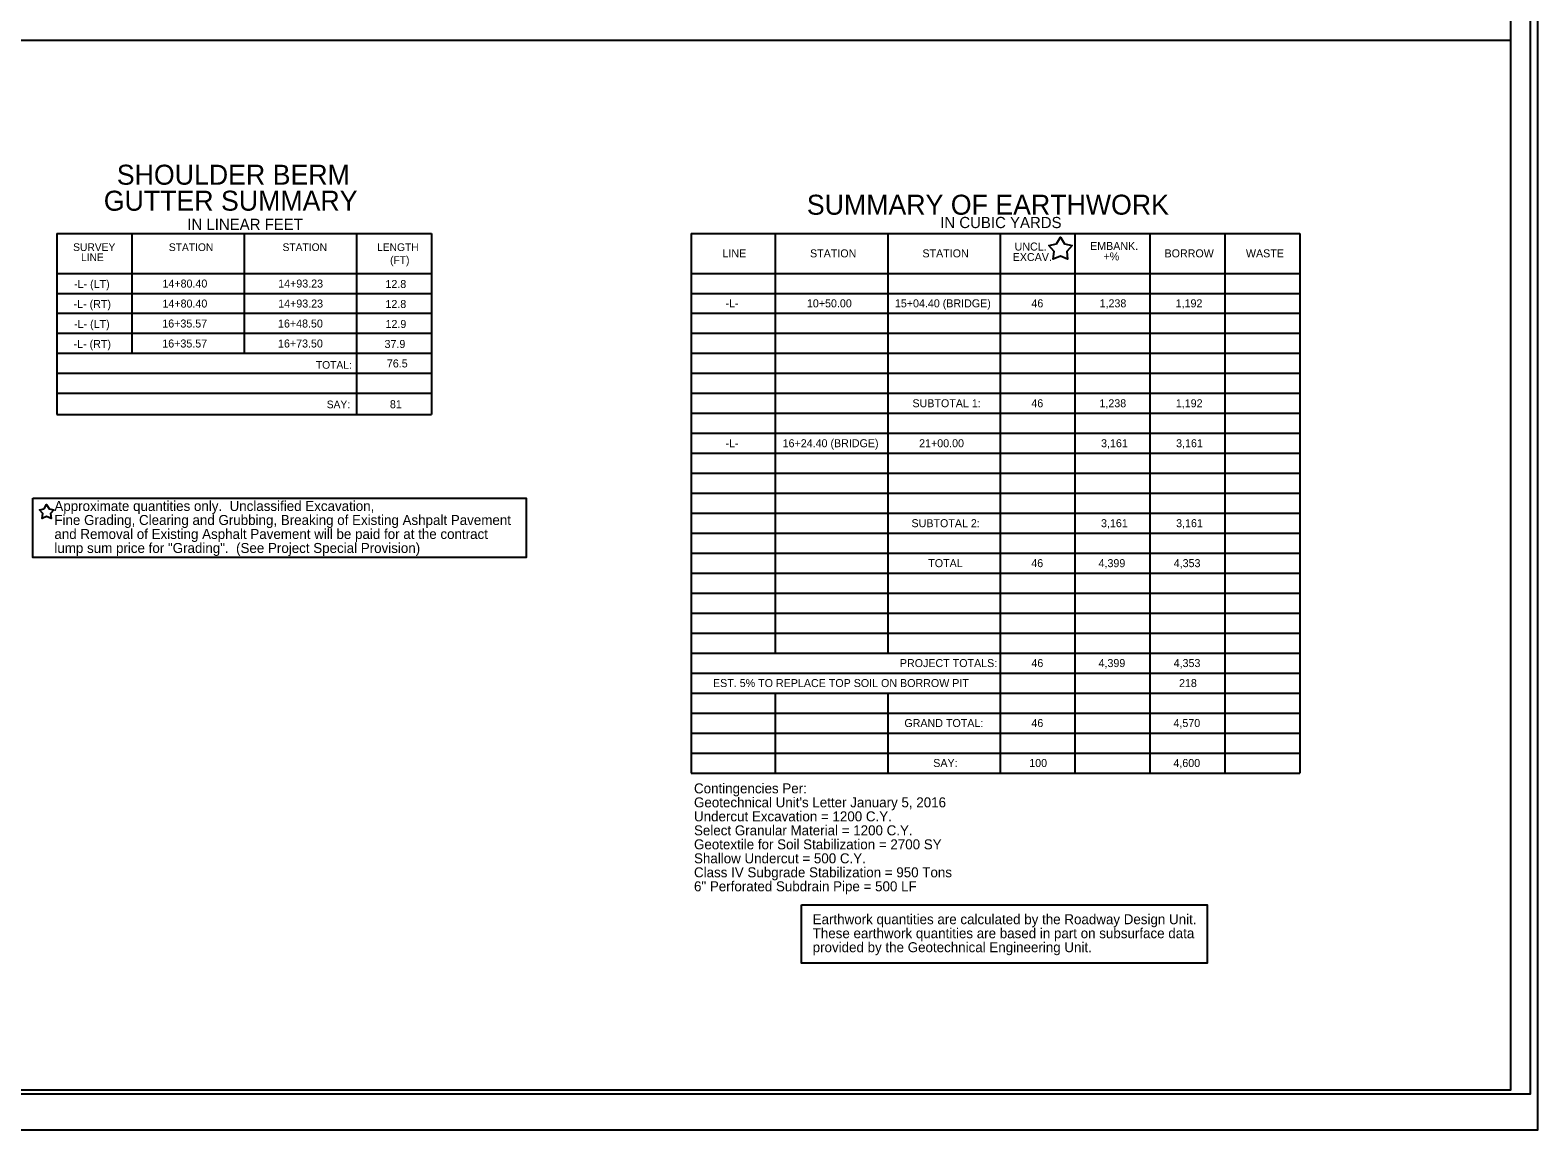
# Model space of a CAD drawing. Extents: x 9833 to 11517, y 9975 to 11331.
# Drawn here: x 10574 to 11517, y 9975 to 10663 of the extents above; entities that cross this region are included whole.
import ezdxf

# ---------------------------------------------------------------- set-up
doc = ezdxf.new("R2010")
doc.units = 0
for name, color, linetype in [('Prop Dimension Text', 7, 'Continuous'), ('Sheet Cutting Line CELL', 7, 'Continuous'), ('Sheet Pipe Summary CELL', 7, 'Continuous'), ('Sheet Plot Border Inside CELL', 7, 'Continuous'), ('Sheet Plot Border Outside CELL', 7, 'Continuous'), ('Sheet Summary CELL', 7, 'Continuous'), ('Sheet Summary Combination CELL', 7, 'Continuous'), ('Sheet Summary Combination Grid CELL', 7, 'Continuous'), ('Sheet Summary Earthwork CELL', 7, 'Continuous')]:
    doc.layers.add(name, color=color, linetype=linetype)

msp = doc.modelspace()

# ---------------------------------------------------------------- linework, layer by layer
at = {"layer": 'Sheet Cutting Line CELL'}
msp.add_line((9833, 9975), (11517, 9975), dxfattribs=at)
at = {"layer": 'Sheet Plot Border Inside CELL'}
msp.add_lwpolyline([(11512.5, 11052.55), (9846, 11052.55), (9846, 9997.45), (11512.5, 9997.45)], close=True, dxfattribs=at)
at = {"layer": 'Sheet Plot Border Outside CELL'}
msp.add_lwpolyline([(11517, 11075), (9833, 11075), (9833, 9975), (11517, 9975)], close=True, dxfattribs=at)
at = {"layer": 'Sheet Summary CELL'}
msp.add_lwpolyline([(11500, 11050), (10000, 11050), (10000, 10000), (11500, 10000)], close=True, dxfattribs=at)
at = {"layer": 'Sheet Summary Combination CELL'}
for p, q in [((10731.53, 10535.63), (10731.53, 10535.63)), ((10737.78, 10535.53), (10737.78, 10535.53)), ((10746.83, 10535.73), (10746.83, 10535.73)), ((10752.43, 10535.63), (10752.43, 10535.63)), ((11134.16, 10535.63), (11134.16, 10535.63)), ((11140.41, 10535.53), (11140.41, 10535.53)), ((11149.46, 10535.73), (11149.46, 10535.73)), ((11155.06, 10535.63), (11155.06, 10535.63))]:
    msp.add_line(p, q, dxfattribs=at)
at = {"layer": 'Sheet Summary Combination Grid CELL'}
for p, q in [((10000, 10656.54), (11500, 10656.54)), ((10590.28, 10535.68), (10824.73, 10535.68)), ((10590.28, 10535.68), (10590.28, 10422.38)), ((10637.18, 10535.68), (10637.18, 10460.68)), ((10707.53, 10535.68), (10707.53, 10460.68)), ((10777.83, 10535.68), (10777.83, 10422.38)), ((10824.73, 10535.68), (10824.73, 10422.38)), ((10987.07, 10535.68), (11368.06, 10535.68)), ((10987.07, 10535.68), (10987.07, 10198.18)), ((11039.81, 10535.68), (11039.81, 10273.18)), ((11110.16, 10535.68), (11110.16, 10273.18)), ((11180.46, 10535.68), (11180.46, 10198.18)), ((11227.36, 10535.68), (11227.36, 10198.18)), ((11274.26, 10535.68), (11274.26, 10198.18)), ((11321.16, 10535.68), (11321.16, 10198.18)), ((11368.06, 10535.68), (11368.06, 10198.18)), ((10590.28, 10510.68), (10824.73, 10510.68)), ((10987.07, 10510.68), (11368.06, 10510.68)), ((10590.28, 10498.18), (10824.73, 10498.18)), ((10987.07, 10498.18), (11368.06, 10498.18)), ((10590.28, 10485.68), (10824.73, 10485.68)), ((10987.07, 10485.68), (11368.06, 10485.68)), ((10590.28, 10473.18), (10824.73, 10473.18)), ((10987.07, 10473.18), (11368.06, 10473.18)), ((10590.28, 10460.68), (10824.73, 10460.68)), ((10987.07, 10460.68), (11368.06, 10460.68)), ((10590.28, 10448.18), (10824.73, 10448.18)), ((10987.07, 10448.18), (11368.06, 10448.18)), ((10590.28, 10435.68), (10824.73, 10435.68)), ((10987.07, 10435.68), (11368.06, 10435.68)), ((10590.28, 10422.38), (10824.73, 10422.38)), ((10987.07, 10423.18), (11368.06, 10423.18)), ((10987.07, 10410.68), (11368.06, 10410.68)), ((10987.07, 10398.18), (11368.06, 10398.18)), ((10987.07, 10385.68), (11368.06, 10385.68)), ((10987.07, 10373.18), (11368.06, 10373.18)), ((10987.07, 10360.68), (11368.06, 10360.68)), ((10987.07, 10348.18), (11368.06, 10348.18)), ((10987.07, 10335.68), (11368.06, 10335.68)), ((10987.07, 10323.18), (11368.06, 10323.18)), ((10987.07, 10310.68), (11368.06, 10310.68)), ((10987.07, 10298.18), (11368.06, 10298.18)), ((10987.07, 10285.68), (11368.06, 10285.68)), ((10987.07, 10273.18), (11368.06, 10273.18)), ((10987.07, 10260.68), (11368.06, 10260.68)), ((10987.07, 10248.18), (11368.06, 10248.18)), ((11039.81, 10248.18), (11039.81, 10198.18)), ((11110.16, 10248.18), (11110.16, 10198.18)), ((10987.07, 10235.68), (11368.06, 10235.68)), ((10987.07, 10223.18), (11368.06, 10223.18)), ((10987.07, 10210.68), (11368.06, 10210.68)), ((10987.07, 10198.18), (11368.06, 10198.18))]:
    msp.add_line(p, q, dxfattribs=at)
at = {"layer": 'Sheet Summary Earthwork CELL'}
for points in [[(11215.83, 10529.07), (11218.28, 10533.32), (11220.73, 10529.07), (11225.53, 10528.05), (11222.25, 10524.41), (11222.76, 10519.53), (11218.28, 10521.52), (11213.8, 10519.53), (11214.31, 10524.41), (11211.03, 10528.05)], [(10575.29, 10370.16), (10883.9, 10370.16), (10883.9, 10332.88), (10575.29, 10332.88)], [(10582.31, 10363.42), (10583.84, 10366.07), (10585.37, 10363.42), (10588.37, 10362.78), (10586.32, 10360.5), (10586.64, 10357.45), (10583.84, 10358.7), (10581.04, 10357.45), (10581.36, 10360.5), (10579.31, 10362.78)], [(11056.19, 10115.71), (11310.14, 10115.71), (11310.14, 10079.31), (11056.19, 10079.31)]]:
    msp.add_lwpolyline(points, close=True, dxfattribs=at)

# ---------------------------------------------------------------- texts
at = {"layer": 'Prop Dimension Text'}
for s, p in [('-L- (LT)', (10601, 10501.52)), ('14+80.40', (10656.32, 10501.8)), ('14+93.23', (10728.74, 10501.8)), ('12.8', (10795.86, 10501.52)), ('-L- (RT)', (10600.71, 10489.02)), ('14+80.40', (10656.32, 10489.3)), ('14+93.23', (10728.74, 10489.3)), ('12.8', (10795.86, 10489.02)), ('-L-', (11008.63, 10489.43)), ('10+50.00', (11059.6, 10489.43)), ('15+04.40 (BRIDGE)', (11114.66, 10489.43)), ('46', (11200.09, 10489.43)), ('1,238', (11242.75, 10489.43)), ('1,192', (11290.35, 10489.43)), ('-L- (LT)', (10601, 10476.52)), ('16+35.57', (10656.21, 10476.8)), ('16+48.50', (10728.63, 10476.8)), ('12.9', (10795.9, 10476.52)), ('-L- (RT)', (10600.71, 10464.02)), ('16+35.57', (10656.21, 10464.3)), ('16+73.50', (10728.63, 10464.3)), ('37.9', (10795.3, 10464.02)), ('76.5', (10796.76, 10451.84)), ('81', (10798.65, 10426.33)), ('46', (11200.05, 10426.93)), ('1,238', (11242.66, 10426.93)), ('1,192', (11290.45, 10426.93)), ('-L-', (11008.63, 10401.93)), ('16+24.40 (BRIDGE)', (11044.41, 10401.93)), ('21+00.00', (11129.82, 10401.93)), ('3,161', (11243.68, 10401.93)), ('3,161', (11290.64, 10401.93)), ('3,161', (11243.65, 10351.93)), ('3,161', (11290.64, 10351.93)), ('46', (11200.01, 10326.93)), ('4,399', (11242.1, 10326.93)), ('4,353', (11289.16, 10326.93)), ('46', (11200.09, 10264.43)), ('4,399', (11242.1, 10264.43)), ('4,353', (11289.09, 10264.43)), ('218', (11292.46, 10251.93)), ('46', (11200.09, 10226.93)), ('4,570', (11288.99, 10226.93)), ('100', (11198.72, 10201.93)), ('4,600', (11288.96, 10201.93))]:
    msp.add_text(s, height=5, dxfattribs=at).set_placement(p)
at = {"layer": 'Sheet Pipe Summary CELL'}
for s, p in [('IN LINEAR FEET', (10671.88, 10537.85)), ('IN CUBIC YARDS', (11143.01, 10538.99))]:
    msp.add_text(s, height=7, dxfattribs=at).set_placement(p)
at = {"layer": 'Sheet Summary Combination CELL'}
for s, p in [('SHOULDER BERM', (10627.76, 10566.12)), ('GUTTER SUMMARY', (10619.59, 10549.86)), ('SUMMARY OF EARTHWORK', (11059.56, 10547.35))]:
    msp.add_text(s, height=12.5001, rotation=0.01193, dxfattribs=at).set_placement(p)
for s, height, p in [('SURVEY', 4.8, (10600.43, 10524.69)), ('STATION', 4.8, (10660.33, 10524.64)), ('STATION', 4.8, (10731.47, 10524.66)), ('LENGTH', 4.8, (10790.6, 10524.66)), ('UNCL.', 5, (11189.57, 10524.95)), ('EMBANK.', 5, (11236.79, 10525.3)), ('LINE', 4.8, (10605.34, 10518.39)), ('LINE', 5, (11006.76, 10520.68)), ('STATION', 5, (11061.56, 10520.68)), ('STATION', 5, (11131.89, 10520.68)), ('EXCAV.', 5, (11188.37, 10518.39)), ('+%', 5, (11245.19, 10518.75)), ('BORROW', 5, (11283.4, 10520.68)), ('WASTE', 5, (11334.33, 10520.68)), ('TOTAL:', 4.8, (10752.34, 10451.03)), ('SAY:', 4.8, (10759.12, 10426.32)), ('SUBTOTAL 1:', 5, (11125.65, 10426.93)), ('SUBTOTAL 2:', 5, (11125.06, 10351.93)), ('TOTAL', 5, (11135.53, 10326.93)), ('PROJECT TOTALS:', 5, (11117.77, 10264.43)), ('EST. 5% TO REPLACE TOP SOIL ON BORROW PIT', 5, (11000.84, 10251.93)), ('GRAND TOTAL:', 5, (11120.59, 10226.93)), ('SAY:', 5, (11138.66, 10201.93))]:
    msp.add_text(s, height=height, dxfattribs=at).set_placement(p)
at = {"layer": 'Sheet Summary Combination Grid CELL'}
msp.add_text('(FT)', height=4.8, dxfattribs=at).set_placement((10798.77, 10516.6))
at = {"layer": 'Sheet Summary Earthwork CELL'}
for s, p in [('Approximate quantities only.  Unclassified Excavation, ', (10588.69, 10362.05)), ('Fine Grading, Clearing and Grubbing, Breaking of Existing Ashpalt Pavement', (10588.69, 10353.3)), ('and Removal of Existing Asphalt Pavement will be paid for at the contract', (10588.69, 10344.55)), ('lump sum price for "Grading".  (See Project Special Provision)', (10588.69, 10335.8)), ('Contingencies Per:', (10988.95, 10185.44)), ("Geotechnical Unit's Letter January 5, 2016", (10988.95, 10176.69)), ('Undercut Excavation = 1200 C.Y.', (10988.95, 10167.94)), ('Select Granular Material = 1200 C.Y.', (10988.95, 10159.19)), ('Geotextile for Soil Stabilization = 2700 SY', (10988.95, 10150.44)), ('Shallow Undercut = 500 C.Y.', (10988.95, 10141.69)), ('Class IV Subgrade Stabilization = 950 Tons', (10988.95, 10132.94)), ('6" Perforated Subdrain Pipe = 500 LF', (10988.95, 10124.19)), ('Earthwork quantities are calculated by the Roadway Design Unit. ', (11063.21, 10103.59)), ('These earthwork quantities are based in part on subsurface data ', (11063.21, 10094.84)), ('provided by the Geotechnical Engineering Unit.', (11063.21, 10086.09))]:
    msp.add_text(s, height=6.25, dxfattribs=at).set_placement(p)

doc.saveas('drawing.dxf')
